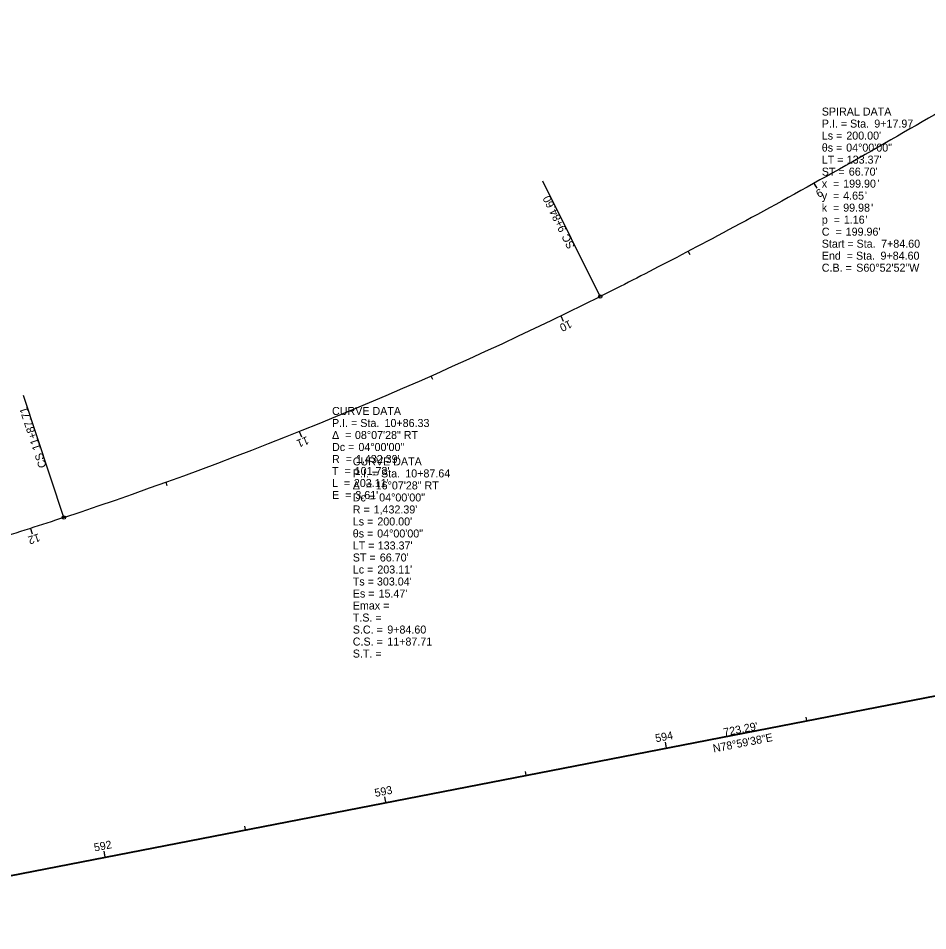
# Model space of a CAD drawing. Extents: x 2255781 to 2266449, y 734189 to 743342.
# Drawn here: x 2262625.7 to 2262943.9, y 741983.3 to 742302.4 of the extents above; entities that cross this region are included whole.
import ezdxf

# ---------------------------------------------------------------- set-up
doc = ezdxf.new("R2010")
doc.units = 0
for name, color, linetype in [('GE_X_Alignment', 7, 'Continuous'), ('GE_X_Alignment_1000_Bearings', 7, 'Continuous'), ('GE_X_Alignment_1000_Cardinal_Points', 7, 'Continuous'), ('GE_X_Alignment_1000_Distances', 7, 'Continuous'), ('GE_X_Alignment_1000_Stations', 7, 'Continuous'), ('GE_X_Alignment_100_Bearings', 7, 'Continuous'), ('GE_X_Alignment_100_Cardinal_Points', 7, 'Continuous'), ('GE_X_Alignment_100_Curve_Data', 7, 'Continuous'), ('GE_X_Alignment_100_Distances', 7, 'Continuous'), ('GE_X_Alignment_100_Stations', 7, 'Continuous'), ('GE_X_Alignment_500_Bearings', 7, 'Continuous'), ('GE_X_Alignment_500_Cardinal_Points', 7, 'Continuous'), ('GE_X_Alignment_500_Curve_Data', 7, 'Continuous'), ('GE_X_Alignment_500_Distances', 7, 'Continuous'), ('GE_X_Alignment_500_Stations', 7, 'Continuous'), ('SC_Scratch4', 7, 'Continuous')]:
    doc.layers.add(name, color=color, linetype=linetype)

msp = doc.modelspace()

# ---------------------------------------------------------------- linework, layer by layer
at = {"layer": 'GE_X_Alignment'}
msp.add_line((2262524.08, 741983.4), (2263234.07, 742121.49), dxfattribs=at)
msp.add_arc((2262191.24, 743487.53), 1432.39, 288.32762, 296.45204, dxfattribs=at)
for points in [[(2263003.98, 742302.4), (2262996.8, 742298.18), (2262982.43, 742289.73), (2262953.66, 742272.9), (2262917.56, 742252.1), (2262881.09, 742231.92), (2262851.61, 742216.36), (2262836.76, 742208.81), (2262829.3, 742205.1)], [(2262641.66, 742127.8), (2262633.75, 742125.18), (2262617.88, 742120.07), (2262585.99, 742110.35), (2262545.9, 742098.99), (2262505.62, 742088.33), (2262473.34, 742080.01), (2262457.2, 742075.88), (2262449.12, 742073.82)]]:
    msp.add_open_spline(points, degree=3, dxfattribs=at)
at = {"layer": 'GE_X_Alignment_1000_Cardinal_Points'}
for p, q in [((2262829.3, 742205.1), (2262809.25, 742245.39)), ((2262641.66, 742127.8), (2262627.51, 742170.51))]:
    msp.add_line(p, q, dxfattribs=at)
for centre in [(2262829.3, 742205.1), (2262641.66, 742127.8)]:
    msp.add_circle(centre, 0.6, dxfattribs=at)
at = {"layer": 'GE_X_Alignment_1000_Stations'}
msp.add_line((2262815.47, 742198.31), (2262816.34, 742196.51), dxfattribs=at)
at = {"layer": 'GE_X_Alignment_100_Cardinal_Points'}
for p, q in [((2262829.3, 742205.1), (2262809.25, 742245.39)), ((2262641.66, 742127.8), (2262627.51, 742170.51))]:
    msp.add_line(p, q, dxfattribs=at)
for centre in [(2262829.3, 742205.1), (2262641.66, 742127.8)]:
    msp.add_circle(centre, 0.6, dxfattribs=at)
at = {"layer": 'GE_X_Alignment_100_Stations'}
for p, q in [((2262904.05, 742244.69), (2262905.03, 742242.94)), ((2262860.1, 742220.86), (2262860.65, 742219.8)), ((2262815.47, 742198.31), (2262816.34, 742196.51)), ((2262770.1, 742177.31), (2262770.58, 742176.21)), ((2262724.02, 742157.91), (2262724.76, 742156.05)), ((2262677.29, 742140.12), (2262677.7, 742139)), ((2262629.97, 742123.98), (2262630.59, 742122.08)), ((2262901.58, 742056.82), (2262901.35, 742058)), ((2262852.5, 742047.28), (2262852.11, 742049.24)), ((2262803.41, 742037.73), (2262803.19, 742038.91)), ((2262754.33, 742028.19), (2262753.95, 742030.15)), ((2262705.25, 742018.64), (2262705.03, 742019.82)), ((2262656.17, 742009.1), (2262655.79, 742011.06))]:
    msp.add_line(p, q, dxfattribs=at)
at = {"layer": 'GE_X_Alignment_500_Cardinal_Points'}
for p, q in [((2262829.3, 742205.1), (2262809.25, 742245.39)), ((2262641.66, 742127.8), (2262627.51, 742170.51))]:
    msp.add_line(p, q, dxfattribs=at)
for centre in [(2262829.3, 742205.1), (2262641.66, 742127.8)]:
    msp.add_circle(centre, 0.6, dxfattribs=at)
at = {"layer": 'GE_X_Alignment_500_Stations'}
for p, q in [((2262904.05, 742244.69), (2262904.64, 742243.64)), ((2262815.47, 742198.31), (2262816.34, 742196.51)), ((2262724.02, 742157.91), (2262724.47, 742156.79)), ((2262629.97, 742123.98), (2262630.34, 742122.84)), ((2262852.5, 742047.28), (2262852.27, 742048.46)), ((2262754.33, 742028.19), (2262754.11, 742029.36)), ((2262656.17, 742009.1), (2262655.94, 742010.27))]:
    msp.add_line(p, q, dxfattribs=at)
at = {"layer": 'SC_Scratch4'}
msp.add_line((2262524.04, 741983.27), (2263234.07, 742121.1), dxfattribs=at)

# ---------------------------------------------------------------- texts
at = {"layer": 'GE_X_Alignment_1000_Bearings'}
msp.add_text('N78°59\'38"E', height=2.8, rotation=11.0061, dxfattribs=at).set_placement((2262869.01, 742045.6))
at = {"layer": 'GE_X_Alignment_1000_Cardinal_Points'}
for s, rotation, p in [('9+84.60', 116.452, (2262817.62, 742228.46)), ('SC', 116.452, (2262820.52, 742222.62)), ('11+87.71', 108.3276, (2262633.64, 742151.84)), ('CS', 108.3276, (2262635.69, 742145.65))]:
    msp.add_text(s, height=2.8, rotation=rotation, dxfattribs=at).set_placement(p)
at = {"layer": 'GE_X_Alignment_1000_Distances'}
msp.add_text("723.29'", height=2.8, rotation=11.0061, dxfattribs=at).set_placement((2262872.7, 742051.25))
at = {"layer": 'GE_X_Alignment_1000_Stations'}
msp.add_text('10', height=2.8, rotation=205.836, dxfattribs=at).set_placement((2262818.56, 742196.97))
at = {"layer": 'GE_X_Alignment_100_Bearings'}
msp.add_text('N78°59\'38"E', height=2.8, rotation=11.0061, dxfattribs=at).set_placement((2262869.01, 742045.6))
at = {"layer": 'GE_X_Alignment_100_Cardinal_Points'}
for s, rotation, p in [('9+84.60', 116.452, (2262817.62, 742228.46)), ('SC', 116.452, (2262820.52, 742222.62)), ('11+87.71', 108.3276, (2262633.64, 742151.84)), ('CS', 108.3276, (2262635.69, 742145.65))]:
    msp.add_text(s, height=2.8, rotation=rotation, dxfattribs=at).set_placement(p)
at = {"layer": 'GE_X_Alignment_100_Curve_Data'}
for s, p in [('SPIRAL DATA', (2262906.81, 742268.36)), ('SPIRAL DATA', (2262906.81, 742268.36)), ('P.I. = Sta. ', (2262906.81, 742264.16)), ('P.I. = Sta. ', (2262906.81, 742264.16)), ('9+17.97', (2262925.17, 742264.16)), ('9+17.97', (2262925.17, 742264.16)), ('Ls = ', (2262906.81, 742259.96)), ('Ls = ', (2262906.81, 742259.96)), ("200.00'", (2262915.39, 742259.96)), ("200.00'", (2262915.39, 742259.96)), ('θs = ', (2262906.81, 742255.76)), ('θs = ', (2262906.81, 742255.76)), ('04°00\'00"', (2262915.34, 742255.76)), ('04°00\'00"', (2262915.34, 742255.76)), ('LT = ', (2262906.81, 742251.56)), ('LT = ', (2262906.81, 742251.56)), ("133.37'", (2262915.54, 742251.56)), ("133.37'", (2262915.54, 742251.56)), ('ST = ', (2262906.81, 742247.36)), ('ST = ', (2262906.81, 742247.36)), ("66.70'", (2262916.26, 742247.36)), ("66.70'", (2262916.26, 742247.36)), ('x  = ', (2262906.81, 742243.16)), ('x  = ', (2262906.81, 742243.16)), ('199.90', (2262914.3, 742243.16)), ('199.90', (2262914.3, 742243.16)), ("'", (2262926.26, 742243.16)), ("'", (2262926.26, 742243.16)), ('y  = ', (2262906.81, 742238.96)), ('y  = ', (2262906.81, 742238.96)), ('4.65', (2262914.3, 742238.96)), ('4.65', (2262914.3, 742238.96)), ("'", (2262921.91, 742238.96)), ("'", (2262921.91, 742238.96)), ('k  = ', (2262906.81, 742234.76)), ('k  = ', (2262906.81, 742234.76)), ('99.98', (2262914.3, 742234.76)), ('99.98', (2262914.3, 742234.76)), ("'", (2262924.09, 742234.76)), ("'", (2262924.09, 742234.76)), ('1.16', (2262914.52, 742230.56)), ('1.16', (2262914.52, 742230.56)), ("'", (2262922.13, 742230.56)), ("'", (2262922.13, 742230.56)), ('p  = ', (2262906.81, 742230.56)), ('p  = ', (2262906.81, 742230.56)), ('C  = ', (2262906.81, 742226.36)), ('C  = ', (2262906.81, 742226.36)), ("199.96'", (2262915.17, 742226.36)), ("199.96'", (2262915.17, 742226.36)), ('Start = Sta. ', (2262906.81, 742222.16)), ('Start = Sta. ', (2262906.81, 742222.16)), ('7+84.60', (2262927.56, 742222.16)), ('7+84.60', (2262927.56, 742222.16)), ('End  = Sta. ', (2262906.81, 742217.96)), ('End  = Sta. ', (2262906.81, 742217.96)), ('9+84.60', (2262927.35, 742217.96)), ('9+84.60', (2262927.35, 742217.96)), ('C.B. = ', (2262906.81, 742213.76)), ('C.B. = ', (2262906.81, 742213.76)), ('S60°52\'52"W', (2262918.87, 742213.76)), ('S60°52\'52"W', (2262918.87, 742213.76)), ('CURVE DATA', (2262735.48, 742163.65)), ('CURVE DATA', (2262735.48, 742163.65)), ('P.I. = Sta. ', (2262735.48, 742159.45)), ('P.I. = Sta. ', (2262735.48, 742159.45)), ('10+86.33', (2262753.84, 742159.45)), ('10+86.33', (2262753.84, 742159.45)), ('Δ  = ', (2262735.48, 742155.25)), ('Δ  = ', (2262735.48, 742155.25)), ('08°07\'28" RT', (2262743.5, 742155.25)), ('08°07\'28" RT', (2262743.5, 742155.25)), ('Dc = ', (2262735.48, 742151.05)), ('Dc = ', (2262735.48, 742151.05)), ('04°00\'00"', (2262744.71, 742151.05)), ('04°00\'00"', (2262744.71, 742151.05)), ('R  = ', (2262735.48, 742146.85)), ('R  = ', (2262735.48, 742146.85)), ('CURVE DATA', (2262742.74, 742146.01)), ('CURVE DATA', (2262742.74, 742146.01)), ("1,432.39'", (2262743.84, 742146.85)), ("1,432.39'", (2262743.84, 742146.85)), ('T  = ', (2262735.48, 742142.65)), ('T  = ', (2262735.48, 742142.65)), ('P.I. = Sta. ', (2262742.74, 742141.81)), ('P.I. = Sta. ', (2262742.74, 742141.81)), ("101.73'", (2262743.41, 742142.65)), ("101.73'", (2262743.41, 742142.65)), ('10+87.64', (2262761.11, 742141.81)), ('10+87.64', (2262761.11, 742141.81)), ('L  = ', (2262735.48, 742138.45)), ('L  = ', (2262735.48, 742138.45)), ("203.11'", (2262743.12, 742138.45)), ("203.11'", (2262743.12, 742138.45)), ('Δ  = ', (2262742.74, 742137.61)), ('Δ  = ', (2262742.74, 742137.61)), ('16°07\'28" RT', (2262750.76, 742137.61)), ('16°07\'28" RT', (2262750.76, 742137.61)), ('E  = ', (2262735.48, 742134.25)), ('E  = ', (2262735.48, 742134.25)), ('Dc = ', (2262742.74, 742133.41)), ('Dc = ', (2262742.74, 742133.41)), ("3.61'", (2262743.63, 742134.25)), ("3.61'", (2262743.63, 742134.25)), ('04°00\'00"', (2262751.98, 742133.41)), ('04°00\'00"', (2262751.98, 742133.41)), ('R = ', (2262742.74, 742129.21)), ('R = ', (2262742.74, 742129.21)), ("1,432.39'", (2262750.02, 742129.21)), ("1,432.39'", (2262750.02, 742129.21)), ('Ls = ', (2262742.74, 742125.01)), ('Ls = ', (2262742.74, 742125.01)), ("200.00'", (2262751.33, 742125.01)), ("200.00'", (2262751.33, 742125.01)), ('θs = ', (2262742.74, 742120.81)), ('θs = ', (2262742.74, 742120.81)), ('04°00\'00"', (2262751.28, 742120.81)), ('04°00\'00"', (2262751.28, 742120.81)), ('LT = ', (2262742.74, 742116.61)), ('LT = ', (2262742.74, 742116.61)), ("133.37'", (2262751.47, 742116.61)), ("133.37'", (2262751.47, 742116.61)), ('ST = ', (2262742.74, 742112.41)), ('ST = ', (2262742.74, 742112.41)), ("66.70'", (2262752.2, 742112.41)), ("66.70'", (2262752.2, 742112.41)), ('Lc = ', (2262742.74, 742108.21)), ('Lc = ', (2262742.74, 742108.21)), ("203.11'", (2262751.33, 742108.21)), ("203.11'", (2262751.33, 742108.21)), ('Ts = ', (2262742.74, 742104.01)), ('Ts = ', (2262742.74, 742104.01)), ("303.04'", (2262751.19, 742104.01)), ("303.04'", (2262751.19, 742104.01)), ('Es = ', (2262742.74, 742099.81)), ('Es = ', (2262742.74, 742099.81)), ("15.47'", (2262751.76, 742099.81)), ("15.47'", (2262751.76, 742099.81)), ('Emax = ', (2262742.74, 742095.61)), ('Emax = ', (2262742.74, 742095.61)), ('T.S. = ', (2262742.74, 742091.41)), ('T.S. = ', (2262742.74, 742091.41)), ('S.C. = ', (2262742.74, 742087.21)), ('S.C. = ', (2262742.74, 742087.21)), ('9+84.60', (2262754.81, 742087.21)), ('9+84.60', (2262754.81, 742087.21)), ('C.S. = ', (2262742.74, 742083.01)), ('C.S. = ', (2262742.74, 742083.01)), ('11+87.71', (2262754.81, 742083.01)), ('11+87.71', (2262754.81, 742083.01)), ('S.T. = ', (2262742.74, 742078.81)), ('S.T. = ', (2262742.74, 742078.81))]:
    msp.add_text(s, height=2.8, dxfattribs=at).set_placement(p)
at = {"layer": 'GE_X_Alignment_100_Distances'}
msp.add_text("723.29'", height=2.8, rotation=11.0061, dxfattribs=at).set_placement((2262872.7, 742051.25))
at = {"layer": 'GE_X_Alignment_100_Stations'}
for s, rotation, p in [('9', 209.1203, (2262906.23, 742242.99)), ('10', 205.836, (2262818.56, 742196.97)), ('11', 201.836, (2262726.69, 742156.29)), ('12', 197.8511, (2262632.82, 742122.27)), ('594', 11.0061, (2262848.83, 742049.16)), ('593', 11.0061, (2262750.64, 742030.06)), ('592', 11.0061, (2262652.47, 742010.97))]:
    msp.add_text(s, height=2.8, rotation=rotation, dxfattribs=at).set_placement(p)
at = {"layer": 'GE_X_Alignment_500_Bearings'}
msp.add_text('N78°59\'38"E', height=2.8, rotation=11.0061, dxfattribs=at).set_placement((2262869.01, 742045.6))
at = {"layer": 'GE_X_Alignment_500_Cardinal_Points'}
for s, rotation, p in [('9+84.60', 116.452, (2262817.62, 742228.46)), ('SC', 116.452, (2262820.52, 742222.62)), ('11+87.71', 108.3276, (2262633.64, 742151.84)), ('CS', 108.3276, (2262635.69, 742145.65))]:
    msp.add_text(s, height=2.8, rotation=rotation, dxfattribs=at).set_placement(p)
at = {"layer": 'GE_X_Alignment_500_Curve_Data'}
for s, p in [('SPIRAL DATA', (2262906.81, 742268.36)), ('P.I. = Sta. ', (2262906.81, 742264.16)), ('9+17.97', (2262925.17, 742264.16)), ('Ls = ', (2262906.81, 742259.96)), ("200.00'", (2262915.39, 742259.96)), ('θs = ', (2262906.81, 742255.76)), ('04°00\'00"', (2262915.34, 742255.76)), ('LT = ', (2262906.81, 742251.56)), ("133.37'", (2262915.54, 742251.56)), ('ST = ', (2262906.81, 742247.36)), ("66.70'", (2262916.26, 742247.36)), ('x  = ', (2262906.81, 742243.16)), ('199.90', (2262914.3, 742243.16)), ("'", (2262926.26, 742243.16)), ('y  = ', (2262906.81, 742238.96)), ('4.65', (2262914.3, 742238.96)), ("'", (2262921.91, 742238.96)), ('k  = ', (2262906.81, 742234.76)), ('99.98', (2262914.3, 742234.76)), ("'", (2262924.09, 742234.76)), ('1.16', (2262914.52, 742230.56)), ("'", (2262922.13, 742230.56)), ('p  = ', (2262906.81, 742230.56)), ('C  = ', (2262906.81, 742226.36)), ("199.96'", (2262915.17, 742226.36)), ('Start = Sta. ', (2262906.81, 742222.16)), ('7+84.60', (2262927.56, 742222.16)), ('End  = Sta. ', (2262906.81, 742217.96)), ('9+84.60', (2262927.35, 742217.96)), ('C.B. = ', (2262906.81, 742213.76)), ('S60°52\'52"W', (2262918.87, 742213.76)), ('CURVE DATA', (2262735.48, 742163.65)), ('P.I. = Sta. ', (2262735.48, 742159.45)), ('10+86.33', (2262753.84, 742159.45)), ('Δ  = ', (2262735.48, 742155.25)), ('08°07\'28" RT', (2262743.5, 742155.25)), ('Dc = ', (2262735.48, 742151.05)), ('04°00\'00"', (2262744.71, 742151.05)), ('R  = ', (2262735.48, 742146.85)), ('CURVE DATA', (2262742.74, 742146.01)), ("1,432.39'", (2262743.84, 742146.85)), ('T  = ', (2262735.48, 742142.65)), ('P.I. = Sta. ', (2262742.74, 742141.81)), ("101.73'", (2262743.41, 742142.65)), ('10+87.64', (2262761.11, 742141.81)), ('L  = ', (2262735.48, 742138.45)), ("203.11'", (2262743.12, 742138.45)), ('Δ  = ', (2262742.74, 742137.61)), ('16°07\'28" RT', (2262750.76, 742137.61)), ('E  = ', (2262735.48, 742134.25)), ('Dc = ', (2262742.74, 742133.41)), ("3.61'", (2262743.63, 742134.25)), ('04°00\'00"', (2262751.98, 742133.41)), ('R = ', (2262742.74, 742129.21)), ("1,432.39'", (2262750.02, 742129.21)), ('Ls = ', (2262742.74, 742125.01)), ("200.00'", (2262751.33, 742125.01)), ('θs = ', (2262742.74, 742120.81)), ('04°00\'00"', (2262751.28, 742120.81)), ('LT = ', (2262742.74, 742116.61)), ("133.37'", (2262751.47, 742116.61)), ('ST = ', (2262742.74, 742112.41)), ("66.70'", (2262752.2, 742112.41)), ('Lc = ', (2262742.74, 742108.21)), ("203.11'", (2262751.33, 742108.21)), ('Ts = ', (2262742.74, 742104.01)), ("303.04'", (2262751.19, 742104.01)), ('Es = ', (2262742.74, 742099.81)), ("15.47'", (2262751.76, 742099.81)), ('Emax = ', (2262742.74, 742095.61)), ('T.S. = ', (2262742.74, 742091.41)), ('S.C. = ', (2262742.74, 742087.21)), ('9+84.60', (2262754.81, 742087.21)), ('C.S. = ', (2262742.74, 742083.01)), ('11+87.71', (2262754.81, 742083.01)), ('S.T. = ', (2262742.74, 742078.81))]:
    msp.add_text(s, height=2.8, dxfattribs=at).set_placement(p)
at = {"layer": 'GE_X_Alignment_500_Distances'}
msp.add_text("723.29'", height=2.8, rotation=11.0061, dxfattribs=at).set_placement((2262872.7, 742051.25))
at = {"layer": 'GE_X_Alignment_500_Stations'}
msp.add_text('10', height=2.8, rotation=205.836, dxfattribs=at).set_placement((2262818.56, 742196.97))

doc.saveas('drawing.dxf')
